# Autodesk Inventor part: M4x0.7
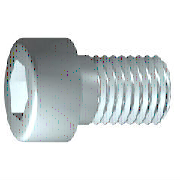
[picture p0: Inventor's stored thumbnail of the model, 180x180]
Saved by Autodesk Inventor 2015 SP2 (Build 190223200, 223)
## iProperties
Created: 2009-02
Part Number: M4x0.7
Material: 강, 연강
Description: 6각머리 태핑 나사
Document SubType Name: Modeling
Standard: KS B 1003
Standards Organization: KS
Language: ko-KR
Size Designation: M 4 x 12
Categories: <MemberInstance><Categories><Category DisplayName="조임쇠" InternalName="e4da775c-781d-43d5-af7c-5136215cf5a6" Mnemonic="FSTN"><Category DisplayName="볼트" InternalN
Density: 1 g/cm^3
Checked By: KYOUNG IL JANG
Vendor: CBT Solutions
Designer: KYOUNG IL JANG
Appearance: _시험-금속-강(연마)
Manager: KYOUNG IL JANG
Company: 한국ATC센터
IsCustomPart: 0
Author: KYOUNG IL JANG
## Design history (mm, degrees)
sketch "스케치1"
  geometry: L1 (-1, 0)-(12, 0); L2 (12, 0)-(12, 2); L3 (12, 2)-(1.75, 2); L4 (1.75, 2)-(1.32, 2); L5 (1.32, 2)-(0, 2); L6 (0, 2)-(0, 3.5); L7 (0, 3.5)-(-4, 3.5); L8 (-4, 3.5)-(-4, 1.732); L9 (-4, 1.732)-(-2, 1.732); L10 (-2, 1.732)-(-1, 0); L11 (-7.2, 0)-(15.2, 0) reference; L12 (0, -0.7)-(0, 4.2) reference; L13 (1.75, 2)-(0, 2)
  constraints: 22 end point, 6 parallel, 2 collinear, 2 perpendicular, 1 horizontal, 1 point on line
  dimensions: "d1" = 10.25 distance from line of L3.end L2 (= GEL); "d2" = 0.42952 distance of L4.end L3.end (computed from GAL); "d3" = 4 distance between parallel lines of L8 L6 (= KOH); "d4" = 2 distance of L8.end L9.end (= INTI); "d5" = 60 deg angle of L10 L1; "d6" = 4 diameter of L3 L1 (= GD); "d7" = 4 diameter of L5 L1 (= BDM); "d8" = 3.4641 diameter of L9 L1 (= 1.1547 x SW); "d9" = 7 diameter of L7 L1 (= KOD); "d26" = 12 distance between parallel lines of L12 L2 (= NLG)
revolve "본체" sketch "스케치1" stored, may be unused: angle "d10" = 90 deg
sketch "스케치2"
  geometry: L1 (0, -4.9)-(0, 4.9) reference; L2 (-4.9, 0)-(4.9, 0) reference; L3 (1.732, 0)-(0.866, -1.5); L4 (0.866, -1.5)-(-0.866, -1.5); L5 (-0.866, -1.5)-(-1.732, 0); L6 (-1.732, 0)-(-0.866, 1.5); L7 (-0.866, 1.5)-(0.866, 1.5); L8 (0.866, 1.5)-(1.732, 0); 2 further points
  constraints: 12 end point, 1 coincident, 1 horizontal alignment, 1 point on line, 12 other
extrude "슬롯" join sketch "스케치2" stored distance "d11" = 10; taper "d12" = 0 deg
workplane "Work Plane1"
fillet "Fillet2" dims "d30" = 0.1 (= R)
body "Solid1"
fillet "모깎기1" dims "d17" = 0.4 (= RR)
feature "스레드" dims "d13" = 10.25 (= GEL), "d14" = 0
chamfer "모따기1" distance "d15" = 0.42941 (= -0.5 x SPD + 0.5 x GD); stored, may be unused: second distance "d16" = 0.42941 (= GUL), angle "d27" = 45 deg
other parameters: "GD" = 4 (= NND) [user parameter; used in 2 equation terms], "NLG" = 12 [user parameter; used in 1 equation term], "GEL" = 10.25 [user parameter; used in 2 equation terms], "KOD" = 7 [user parameter; used in 1 equation term], "KOH" = 4 [user parameter; used in 1 equation term], "INTI" = 2 [user parameter; used in 1 equation term], "GAL" = 0.42941 (= 0.61345 x PTC) [user parameter; used in 1 equation term], "GUL" = 0.42941 (= 0.61345 x PTC) [user parameter; used in 1 equation term], "BDM" = 4 (= NND) [user parameter; used in 1 equation term], "SW" = 3 [user parameter; used in 2 equation terms], "RR" = 0.4 [user parameter; used in 1 equation term], "SPD" = 3.14117 (= NND - 1.2269 x PTC) [user parameter; used in 1 equation term], "d19" = 0, "d28" = 0, "d29" = 0, "R" = 0.1 [user parameter; used in 1 equation term], "PHH" = 0.2 [user parameter], "GD1" = 3.14117 (= THREADDIA - 1.2269 x PTC) [user parameter], "THREADDIA" = 4 [user parameter; used in 1 equation term], "FAWI" = 45 deg [user parameter], "TPU" = 14.28571 (computed from PTC) [user parameter], "PTC" = 0.7 [user parameter; used in 5 equation terms], "NND" = 4 [user parameter; used in 3 equation terms], "TOA" = 30 deg [user parameter], "E0" = 3.465 (= 1.155 x SW) [user parameter]
